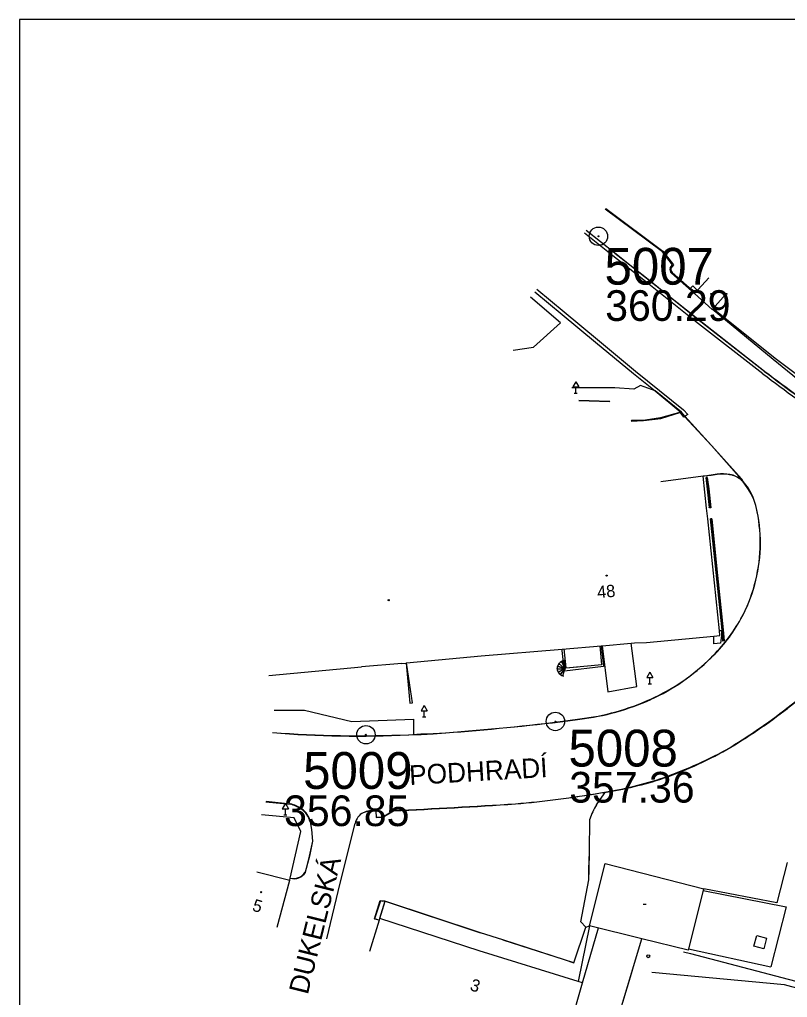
# Model space of a CAD drawing. Extents: x -590420 to -590210, y -1129531 to -1129234.
# Drawn here: x -590420.4 to -590357.8, y -1129313.6 to -1129233.9 of the extents above; entities that cross this region are included whole.
import ezdxf

# ---------------------------------------------------------------- set-up
doc = ezdxf.new("R2010")
doc.units = 0
for name, color, linetype in [('Vrstva 10', 7, 'Continuous'), ('Vrstva 15', 7, 'Continuous'), ('Vrstva 17', 7, 'Continuous'), ('Vrstva 19', 7, 'Continuous'), ('Vrstva 23', 7, 'Continuous'), ('Vrstva 4', 7, 'Continuous'), ('Vrstva 42', 7, 'Continuous'), ('Vrstva 43', 7, 'Continuous'), ('Vrstva 5', 7, 'Continuous'), ('Vrstva 63', 7, 'Continuous'), ('Vrstva 7', 7, 'Continuous'), ('Vrstva 9', 7, 'Continuous'), ('Vrstva B58', 7, 'Continuous'), ('Vrstva B59', 7, 'Continuous'), ('Vrstva B60', 7, 'Continuous')]:
    doc.layers.add(name, color=color, linetype=linetype)

msp = doc.modelspace()

# ---------------------------------------------------------------- linework, layer by layer
at = {"layer": 'Vrstva 10'}
for points in [[(-590357.78, -1129302.59), (-590358.63, -1129305.87), (-590364.59, -1129304.72)], [(-590373.92, -1129307.73), (-590374.832, -1129312.271)], [(-590366.23, -1129309.858), (-590365.68, -1129310.01), (-590339.47, -1129316.88), (-590321.05, -1129317.64), (-590313.58, -1129317.8), (-590297.47, -1129317.49), (-590297.03, -1129314.18)]]:
    msp.add_lwpolyline(points, dxfattribs=at)
at = {"layer": 'Vrstva 15'}
msp.add_line((-590369.539, -1129305.984), (-590369.289, -1129305.984), dxfattribs=at)
for centre in [(-590363.98, -1129256.221), (-590362.747, -1129256.221), (-590372.51, -1129279.184), (-590390.291, -1129281.192), (-590400.688, -1129304.994)]:
    msp.add_circle(centre, 0.0438, dxfattribs=at)
at = {"layer": 'Vrstva 17'}
for p, q in [((-590365.34, -1129256.2), (-590367.22, -1129254.53)), ((-590367.169, -1129254.474), (-590365.289, -1129256.144)), ((-590365.289, -1129256.144), (-590365.289, -1129256.144))]:
    msp.add_line(p, q, dxfattribs=at)
for points in [[(-590367.34, -1129254.09), (-590367.14, -1129253.84), (-590367.96, -1129252.78), (-590372.63, -1129249.32)], [(-590372.59, -1129249.27), (-590367.92, -1129252.73), (-590367.063, -1129253.838), (-590367.269, -1129254.108)], [(-590354.37, -1129264.78), (-590354.53, -1129265.04), (-590355.43, -1129264.41), (-590358.93, -1129261.58), (-590363.889, -1129257.476), (-590363.823, -1129257.404)], [(-590363.823, -1129257.404), (-590358.76, -1129261.47), (-590355.1, -1129264.21), (-590354.37, -1129264.78)]]:
    msp.add_lwpolyline(points, dxfattribs=at)
for centre, major_axis in [((-590366.905, -1129254.211), (0.226, -0.395)), ((-590366.907, -1129254.208), (0.188, -0.329))]:
    msp.add_ellipse(centre, major_axis=major_axis, ratio=0.984986, start_param=3.930118, end_param=4.981494, dxfattribs=at)
at = {"layer": 'Vrstva 19'}
for p, q in [((-590375.03, -1129263.377), (-590375.28, -1129263.81)), ((-590375.03, -1129263.377), (-590374.78, -1129263.81)), ((-590375.28, -1129263.81), (-590374.78, -1129263.81)), ((-590375.155, -1129264.31), (-590374.905, -1129264.31)), ((-590375.03, -1129264.31), (-590375.03, -1129263.81)), ((-590368.99, -1129287.067), (-590369.24, -1129287.5)), ((-590368.99, -1129287.067), (-590368.74, -1129287.5)), ((-590369.24, -1129287.5), (-590368.74, -1129287.5)), ((-590369.115, -1129288), (-590368.865, -1129288)), ((-590368.99, -1129288), (-590368.99, -1129287.5)), ((-590387.4, -1129289.767), (-590387.65, -1129290.2)), ((-590387.4, -1129289.767), (-590387.15, -1129290.2)), ((-590387.65, -1129290.2), (-590387.15, -1129290.2)), ((-590387.4, -1129290.7), (-590387.4, -1129290.2)), ((-590387.525, -1129290.7), (-590387.275, -1129290.7)), ((-590398.72, -1129297.767), (-590398.97, -1129298.2)), ((-590398.72, -1129297.767), (-590398.47, -1129298.2)), ((-590398.97, -1129298.2), (-590398.47, -1129298.2)), ((-590398.72, -1129298.7), (-590398.72, -1129298.2)), ((-590398.845, -1129298.7), (-590398.595, -1129298.7))]:
    msp.add_line(p, q, dxfattribs=at)
at = {"layer": 'Vrstva 23'}
for points in [[(-590365.659, -1129255.755), (-590365.289, -1129256.09), (-590365.121, -1129255.905), (-590365.491, -1129255.57)], [(-590360.5, -1129309.4), (-590360.27, -1129308.54), (-590359.459, -1129308.756), (-590359.689, -1129309.616)]]:
    msp.add_lwpolyline(points, close=True, dxfattribs=at)
msp.add_circle((-590369.12, -1129310.22), 0.125, dxfattribs=at)
at = {"layer": 'Vrstva 4'}
for p, q in [((-590364.177, -1129254.921), (-590365.34, -1129256.2)), ((-590363.91, -1129257.5), (-590365.34, -1129256.2)), ((-590362.747, -1129256.221), (-590363.91, -1129257.5)), ((-590400.07, -1129287.32), (-590392.51, -1129286.63)), ((-590376.524, -1129286.567), (-590375.948, -1129286.767)), ((-590376.398, -1129286.364), (-590375.94, -1129286.754)), ((-590376.205, -1129286.201), (-590375.928, -1129286.744)), ((-590376.56, -1129286.827), (-590375.95, -1129286.783)), ((-590376.472, -1129287.067), (-590375.946, -1129286.798)), ((-590376.297, -1129287.249), (-590375.935, -1129286.811)), ((-590376.077, -1129287.366), (-590375.921, -1129286.818)), ((-590375.947, -1129286.795), (-590375.947, -1129286.795)), ((-590375.873, -1129286.765), (-590375.873, -1129286.765)), ((-590401.06, -1129303.331), (-590398.36, -1129304.02)), ((-590399.38, -1129307.86), (-590398.36, -1129304.02))]:
    msp.add_line(p, q, dxfattribs=at)
for points in [[(-590389.22, -1129286.35), (-590388.86, -1129286.316), (-590388.827, -1129286.312), (-590382.74, -1129285.73), (-590376.138, -1129285.175), (-590372.968, -1129284.909), (-590372.875, -1129284.901), (-590370.509, -1129284.703), (-590370.24, -1129284.68), (-590369.25, -1129284.63), (-590363.77, -1129284.117), (-590363.27, -1129284.07), (-590363.31, -1129283.685), (-590363.857, -1129278.466), (-590364.267, -1129274.55), (-590364.358, -1129273.688), (-590364.63, -1129271.09), (-590368.08, -1129271.54)], [(-590376.014, -1129285.165), (-590375.83, -1129286.71), (-590372.9, -1129286.44), (-590373.028, -1129284.914)], [(-590372.875, -1129284.901), (-590372.41, -1129288.66), (-590370.04, -1129288.24), (-590370.509, -1129284.703)], [(-590386.47, -1129329.57), (-590381.1, -1129331.63), (-590378.34, -1129325.04), (-590372.97, -1129326.72), (-590372.97, -1129326.71), (-590371.23, -1129321.27), (-590370.254, -1129318.212), (-590370.11, -1129317.76), (-590370.282, -1129317.698), (-590370.284, -1129317.695), (-590372.104, -1129317.046), (-590372.11, -1129317.05), (-590375.5, -1129315.91), (-590374.48, -1129312.38), (-590374.832, -1129312.271), (-590382.92, -1129309.78), (-590391.013, -1129307.149), (-590391.04, -1129307.14), (-590391.04, -1129307.14), (-590391.078, -1129307.264), (-590391.08, -1129307.272), (-590391.87, -1129309.84)]]:
    msp.add_lwpolyline(points, dxfattribs=at)
msp.add_lwpolyline([(-590372.64, -1129302.65), (-590364.59, -1129304.72), (-590364.625, -1129304.857), (-590365.83, -1129309.614), (-590365.86, -1129309.73), (-590369.649, -1129308.79), (-590373.92, -1129307.73)], close=True, dxfattribs=at)
msp.add_circle((-590375.91, -1129286.78), 0.04, dxfattribs=at)
msp.add_circle((-590375.91, -1129286.78), 0.04, dxfattribs=at)
for start, end in [(215.00782, 232.94293), (232.94293, 250.60717)]:
    msp.add_arc((-590375.809, -1129286.602), 0.81, start, end, dxfattribs=at)
at = {"layer": 'Vrstva 5'}
for p, q in [((-590375.948, -1129286.767), (-590376.524, -1129286.567)), ((-590376.524, -1129286.567), (-590376.524, -1129286.567)), ((-590375.94, -1129286.754), (-590376.398, -1129286.364)), ((-590376.398, -1129286.364), (-590376.398, -1129286.364)), ((-590376.205, -1129286.201), (-590375.883, -1129286.07)), ((-590375.928, -1129286.744), (-590376.205, -1129286.201)), ((-590376.205, -1129286.201), (-590376.205, -1129286.201)), ((-590375.976, -1129286.108), (-590375.914, -1129286.74)), ((-590375.976, -1129286.108), (-590375.976, -1129286.108)), ((-590375.83, -1129286.71), (-590374.884, -1129286.623)), ((-590374.884, -1129286.623), (-590374.884, -1129286.623)), ((-590375.95, -1129286.783), (-590376.56, -1129286.827)), ((-590376.56, -1129286.827), (-590376.56, -1129286.827)), ((-590375.946, -1129286.798), (-590376.472, -1129287.067)), ((-590376.472, -1129287.067), (-590376.472, -1129287.067)), ((-590375.935, -1129286.811), (-590376.297, -1129287.249)), ((-590376.297, -1129287.249), (-590376.297, -1129287.249)), ((-590376.077, -1129287.366), (-590376.077, -1129287.366)), ((-590375.83, -1129286.71), (-590375.83, -1129286.71))]:
    msp.add_line(p, q, dxfattribs=at)
msp.add_lwpolyline([(-590389.22, -1129286.35), (-590392.51, -1129286.63)], dxfattribs=at)
for centre, radius, start, end in [((-590376.027, -1129286.768), 0.536, 158.02047, 186.35954), ((-590375.797, -1129286.878), 0.791, 139.43926, 156.88044), ((-590375.797, -1129286.878), 0.791, 121.10978, 139.43926), ((-590375.797, -1129286.878), 0.791, 103.07973, 121.10978), ((-590376.027, -1129286.768), 0.536, 186.35954, 213.92649)]:
    msp.add_arc(centre, radius, start, end, dxfattribs=at)
for centre, major_axis, ratio, start_param, end_param in [((-590375.754, -1129286.753), (-0.808, -0.043), 0.804719, 5.928327, 6.719832), ((-590375.441, -1129287.099), (-1.027, 0.639), 0.799712, 5.902988, 6.408068), ((-590375.573, -1129286.258), (-0.693, -1.013), 0.808425, 5.991235, 6.532866)]:
    msp.add_ellipse(centre, major_axis=major_axis, ratio=ratio, start_param=start_param, end_param=end_param, dxfattribs=at)
at = {"layer": 'Vrstva 63'}
for p, q in [((-590210.408, -1129233.852), (-590420.408, -1129233.852)), ((-590420.408, -1129233.852), (-590420.408, -1129530.852))]:
    msp.add_line(p, q, dxfattribs=at)
at = {"layer": 'Vrstva 7'}
for p, q in [((-590378.37, -1129256.06), (-590376.13, -1129257.91)), ((-590378.36, -1129256.04), (-590376.13, -1129257.91)), ((-590371.83, -1129263.89), (-590375.35, -1129263.89)), ((-590374.78, -1129264.88), (-590372.269, -1129264.959)), ((-590366.202, -1129266.264), (-590366.501, -1129265.872)), ((-590366.202, -1129266.267), (-590366.501, -1129265.872)), ((-590366.449, -1129265.855), (-590366.162, -1129266.227)), ((-590366.13, -1129266.2), (-590366.41, -1129265.87)), ((-590370.49, -1129266.55), (-590370.52, -1129266.6)), ((-590366.15, -1129266.22), (-590366.202, -1129266.267)), ((-590361.54, -1129271.39), (-590361.38, -1129271.54)), ((-590361.53, -1129271.37), (-590361.36, -1129271.52)), ((-590361.36, -1129271.52), (-590361.5, -1129271.35)), ((-590361.36, -1129271.52), (-590361.49, -1129271.33)), ((-590360.98, -1129272.08), (-590361.38, -1129271.54)), ((-590360.95, -1129272.07), (-590361.36, -1129271.52)), ((-590364.147, -1129273.658), (-590364.141, -1129273.648)), ((-590364.131, -1129273.657), (-590364.127, -1129273.648)), ((-590364.02, -1129273.65), (-590364.131, -1129273.657)), ((-590364.041, -1129273.643), (-590364.127, -1129273.648)), ((-590364.02, -1129273.65), (-590364.041, -1129273.643)), ((-590363.94, -1129274.55), (-590364.048, -1129274.558)), ((-590364.048, -1129274.558), (-590364.036, -1129274.568)), ((-590363.95, -1129274.56), (-590364.036, -1129274.568)), ((-590363.95, -1129274.56), (-590363.94, -1129274.55)), ((-590363.14, -1129283.68), (-590363.31, -1129283.685)), ((-590372.968, -1129284.909), (-590372.77, -1129286.61)), ((-590362.93, -1129284.51), (-590363.03, -1129284.519)), ((-590357.8, -1129289.99), (-590352.24, -1129285.71)), ((-590352.24, -1129285.73), (-590357.76, -1129290.01)), ((-590375.69, -1129291.04), (-590374.7, -1129290.9)), ((-590375.68, -1129291.01), (-590374.7, -1129290.87)), ((-590400.32, -1129297.63), (-590398.32, -1129297.82)), ((-590400.3, -1129297.59), (-590398.31, -1129297.8)), ((-590391.34, -1129298.39), (-590391.354, -1129298.407)), ((-590396.71, -1129299.27), (-590396.59, -1129299.9)), ((-590396.56, -1129299.89), (-590396.68, -1129299.27)), ((-590396.48, -1129300.84), (-590396.56, -1129299.89)), ((-590391.013, -1129307.149), (-590390.58, -1129305.74)), ((-590390.99, -1129305.67), (-590390.8, -1129305.74)), ((-590390.6, -1129305.73), (-590390.58, -1129305.74)), ((-590391.46, -1129307.18), (-590391.455, -1129307.176)), ((-590374.48, -1129312.38), (-590373.166, -1129307.917)), ((-590374.21, -1129307.86), (-590373.92, -1129307.73)), ((-590372.104, -1129317.046), (-590369.649, -1129308.79)), ((-590365.83, -1129309.614), (-590359.109, -1129311.088)), ((-590372.11, -1129317.05), (-590370.41, -1129311.35))]:
    msp.add_line(p, q, dxfattribs=at)
for points in [[(-590359.77, -1129262.73), (-590365.26, -1129258.46), (-590369.6, -1129255), (-590372, -1129253.11), (-590374.33, -1129251.27)], [(-590359.62, -1129262.54), (-590365.08, -1129258.29), (-590369.42, -1129254.82), (-590371.84, -1129252.89), (-590374.17, -1129251.04)], [(-590371.84, -1129252.89), (-590369.4, -1129254.81), (-590365.08, -1129258.27), (-590359.6, -1129262.54)], [(-590378.21, -1129255.83), (-590375.98, -1129257.69), (-590373.27, -1129259.95), (-590370.16, -1129262.52), (-590366.23, -1129265.66), (-590365.89, -1129266.05), (-590366.13, -1129266.2)], [(-590376.13, -1129257.91), (-590373.42, -1129260.15), (-590370.31, -1129262.72), (-590368.56, -1129264.11)], [(-590368.56, -1129264.11), (-590369.76, -1129263.68), (-590370.3, -1129263.98), (-590371.83, -1129263.89)], [(-590366.41, -1129265.87), (-590368.56, -1129264.11)], [(-590368.56, -1129264.11), (-590366.449, -1129265.855)], [(-590374.78, -1129264.91), (-590372.26, -1129264.98), (-590372.269, -1129264.959)], [(-590370.52, -1129266.6), (-590369.51, -1129266.55), (-590368.09, -1129266.39), (-590366.449, -1129265.855)], [(-590366.449, -1129265.855), (-590368.11, -1129266.33), (-590369.53, -1129266.54), (-590370.49, -1129266.55)], [(-590366.162, -1129266.227), (-590366.202, -1129266.264), (-590366.202, -1129266.267)], [(-590366.13, -1129266.2), (-590366.15, -1129266.22), (-590366.162, -1129266.227)], [(-590361.5, -1129271.35), (-590363.97, -1129268.59), (-590366.15, -1129266.22)], [(-590366.13, -1129266.2), (-590363.95, -1129268.58), (-590361.49, -1129271.33)], [(-590363.49, -1129270.92), (-590363.98, -1129271), (-590364.52, -1129271.07), (-590364.63, -1129271.09)], [(-590363.49, -1129270.95), (-590363.99, -1129271.02), (-590364.52, -1129271.08), (-590364.63, -1129271.09)], [(-590364.3, -1129271.19), (-590364.399, -1129271.201)], [(-590364.399, -1129271.201), (-590364.285, -1129272.131), (-590364.131, -1129273.657)], [(-590364.127, -1129273.648), (-590364.279, -1129272.141), (-590364.399, -1129271.201)], [(-590364.3, -1129271.19), (-590364.18, -1129272.12), (-590364.02, -1129273.65)], [(-590364.041, -1129273.643), (-590364.18, -1129272.13), (-590364.3, -1129271.19)], [(-590363.03, -1129284.519), (-590363.097, -1129283.63), (-590363.64, -1129278.407), (-590364.048, -1129274.558)], [(-590364.036, -1129274.568), (-590363.63, -1129278.405), (-590363.09, -1129283.627), (-590363.03, -1129284.519)], [(-590362.93, -1129284.51), (-590363.02, -1129283.62), (-590363.55, -1129278.4), (-590363.95, -1129274.56)], [(-590363.94, -1129274.55), (-590363.54, -1129278.4), (-590363, -1129283.62), (-590362.93, -1129284.51)], [(-590363.14, -1129283.68), (-590363.15, -1129284.07), (-590363.21, -1129284.7), (-590363.77, -1129284.75), (-590363.77, -1129284.117)], [(-590372.77, -1129286.61), (-590375.95, -1129286.98), (-590376.13, -1129285.29), (-590376.138, -1129285.175)], [(-590388.86, -1129286.316), (-590388.56, -1129289.59), (-590388.36, -1129289.57), (-590388.827, -1129286.312)], [(-590399.63, -1129290.16), (-590397.15, -1129290.16), (-590393.301, -1129291.094), (-590388.27, -1129290.89), (-590388.26, -1129292.02), (-590388.259, -1129292.136)], [(-590388.67, -1129292.18), (-590387.64, -1129292.14), (-590386.67, -1129292.08), (-590385.65, -1129292.01)], [(-590388.65, -1129292.16), (-590387.66, -1129292.1), (-590386.66, -1129292.05), (-590385.64, -1129292)], [(-590373.35, -1129297.88), (-590372.72, -1129296.99), (-590372.621, -1129296.851)], [(-590391.354, -1129298.407), (-590391.326, -1129298.897), (-590390.77, -1129298.88), (-590389.89, -1129298.36)], [(-590391.34, -1129298.39), (-590391.32, -1129298.89), (-590390.79, -1129298.87), (-590389.92, -1129298.34)], [(-590395.33, -1129308.81), (-590394.24, -1129304.25), (-590393.02, -1129299.39)], [(-590373.96, -1129303.98), (-590373.96, -1129303.16), (-590373.92, -1129301.7), (-590373.87, -1129299.04)], [(-590373.96, -1129303.98), (-590373.95, -1129303.16), (-590373.9, -1129301.71), (-590373.87, -1129299.04)], [(-590396.59, -1129299.9), (-590396.5, -1129300.83), (-590396.76, -1129302.06), (-590397.11, -1129303.37)], [(-590397.08, -1129303.38), (-590396.75, -1129302.07), (-590396.48, -1129300.84)], [(-590375.18, -1129310.76), (-590374.21, -1129307.86), (-590374.61, -1129307.41), (-590373.96, -1129303.98)], [(-590364.625, -1129304.857), (-590357.86, -1129306.2), (-590359.109, -1129311.088)], [(-590391.08, -1129307.272), (-590391.46, -1129307.18), (-590390.99, -1129305.67)], [(-590390.97, -1129305.69), (-590391.455, -1129307.176), (-590391.078, -1129307.264)], [(-590390.6, -1129305.73), (-590391.047, -1129307.138), (-590391.04, -1129307.14)], [(-590390.6, -1129305.73), (-590390.8, -1129305.74), (-590390.97, -1129305.69), (-590390.99, -1129305.67)], [(-590382.79, -1129308.3), (-590390.6, -1129305.73)], [(-590390.58, -1129305.74), (-590382.8, -1129308.32), (-590382.79, -1129308.3)], [(-590380.97, -1129308.89), (-590382.8, -1129308.32)], [(-590380.97, -1129308.88), (-590382.79, -1129308.3)], [(-590375.18, -1129310.76), (-590375.96, -1129310.51), (-590380.97, -1129308.88)], [(-590380.97, -1129308.88), (-590380.97, -1129308.89), (-590375.97, -1129310.5), (-590375.18, -1129310.76)], [(-590300.68, -1129317.99), (-590311.82, -1129318.26), (-590320.49, -1129318.55), (-590330.07, -1129318.36), (-590338.22, -1129317.93), (-590347.27, -1129315.46), (-590357.99, -1129312.56), (-590368.83, -1129311.54)]]:
    msp.add_lwpolyline(points, dxfattribs=at)
for centre, major_axis, ratio, start_param, end_param in [((-590290.666, -1129172.172), (113.957, 0), 0.999394, 4.060851, 4.121508), ((-590311.072, -1129200.348), (74.306, -27.239), 0.996591, 4.401942, 4.489079), ((-590300.332, -1129185.077), (-91.864, -32.809), 0.999599, 0.574857, 0.645547), ((-590362.993, -1129274.87), (-3.455, 2.106), 0.973966, 5.112478, 5.372051), ((-590363.035, -1129273.709), (1.136, 2.566), 0.988802, 0.219997, 0.585453), ((-590362.721, -1129272.728), (-1.636, 0.749), 0.990971, 4.421053, 5.003725), ((-590362.668, -1129272.607), (-1.658, 0.585), 0.948537, 4.326719, 4.910517), ((-590365.286, -1129274.859), (5.04, -0.98), 0.996227, 0.365497, 0.767095), ((-590365.193, -1129274.73), (-4.08, 2.964), 0.992083, 3.927767, 4.332557), ((-590372.567, -1129276.594), (11.344, 5.528), 0.993582, 5.798102, 6.038644), ((-590373.03, -1129276.573), (11.435, 6.325), 0.993586, 5.745474, 5.975994), ((-590373.185, -1129276.456), (12.742, -3.475), 0.995904, 6.055982, 6.512151), ((-590373.262, -1129276.454), (13.028, 2.703), 0.995054, 5.585564, 6.039391), ((-590372.383, -1129277.107), (10.93, 5.734), 0.982467, 4.984436, 5.314463), ((-590373.77, -1129275.904), (13.994, 0.422), 0.995021, 5.455693, 5.743261), ((-590375.816, -1129274.26), (16.515, 2.292), 0.99106, 5.002119, 5.361718), ((-590375.655, -1129274.352), (16.378, 1.772), 0.992013, 5.027401, 5.392437), ((-590376.962, -1129271.76), (16.097, -10.585), 0.998099, 5.410971, 5.724683), ((-590377.203, -1129270.733), (5.463, -19.574), 0.998752, 6.13435, 6.431051), ((-590387.046, -1129253.843), (43.853, 20.728), 0.956309, 4.818033, 4.941033), ((-590386.782, -1129253.578), (44.345, 17.54), 0.97467, 4.875795, 5.001317), ((-590403.376, -1129067.762), (221.308, -47.672), 0.993086, 5.001538, 5.045774), ((-590401.193, -1129090.944), (189.678, -70.279), 0.996273, 5.143009, 5.192531), ((-590392.84, -1129199.439), (92.402, -14.632), 0.991794, 4.794006, 4.912976), ((-590392.916, -1129205.065), (86.565, -14.731), 0.992946, 4.801627, 4.92816), ((-590378.712, -1129264.919), (30.37, -12.04), 0.998305, 5.41755, 5.601588), ((-590378.794, -1129264.188), (14.898, -29.795), 0.999049, 6.143999, 6.323448), ((-590377.597, -1129265.776), (20.668, -23.749), 0.998615, 5.712701, 5.870381), ((-590377.655, -1129266.212), (-9.931, -29.416), 0.998638, 0.476678, 0.636849), ((-590387.902, -1129209.9), (81.321, -34.813), 0.996917, 5.205705, 5.28511), ((-590388.551, -1129205.369), (86.764, -33.731), 0.996513, 5.174568, 5.249808), ((-590398.987, -1129300.494), (-2.607, 1.171), 0.963267, 4.540823, 4.883955), ((-590398.814, -1129300.156), (-2.156, 1.133), 0.9882, 4.575163, 4.982286), ((-590423.495, -1128784.686), (599.959, 0), 0.857493, 4.76838, 4.785016), ((-590405.778, -1129025.028), (325.315, 2.538), 0.841291, 4.754684, 4.785303), ((-590398.352, -1129299.619), (-1.397, 0.936), 0.996426, 3.943029, 4.719956), ((-590398.274, -1129299.575), (-0.103, 1.621), 0.998972, 4.838094, 5.658591), ((-590391.82, -1129299.605), (-1.191, -0.263), 0.997524, 4.963157, 5.887239), ((-590391.637, -1129300.158), (-1.426, 1.09), 0.998498, 5.197961, 5.785113), ((-590391.594, -1129300.545), (-2.349, -0.052), 0.914057, 4.589447, 5.028392), ((-590368.441, -1129300.777), (-4.743, 3.162), 0.999873, 0.054801, 0.278324), ((-590398.023, -1129302.786), (1.108, 0.12), 0.999611, 4.331448, 5.612957), ((-590398.034, -1129302.795), (0.254, 1.059), 0.999554, 3.110086, 4.390849)]:
    msp.add_ellipse(centre, major_axis=major_axis, ratio=ratio, start_param=start_param, end_param=end_param, dxfattribs=at)
at = {"layer": 'Vrstva 9'}
for points in [[(-590380.14, -1129260.82), (-590378.48, -1129260.56), (-590376.27, -1129258.57), (-590378.73, -1129256.49)], [(-590398.36, -1129304.02), (-590398.324, -1129303.859), (-590398.321, -1129303.845), (-590397.47, -1129300.06), (-590397.99, -1129298.93), (-590400.66, -1129298.69)]]:
    msp.add_lwpolyline(points, dxfattribs=at)
at = {"layer": 'Vrstva B60'}
for centre, radius in [((-590373.18, -1129251.52), 0.75), ((-590373.18, -1129251.52), 0.0358), ((-590376.69, -1129291.08), 0.75), ((-590392.15, -1129292.16), 0.75), ((-590376.69, -1129291.08), 0.0358), ((-590392.15, -1129292.16), 0.0358)]:
    msp.add_circle(centre, radius, dxfattribs=at)

# ---------------------------------------------------------------- texts
at = {"layer": 'Vrstva 42'}
for s, rotation, p in [('PODHRADÍ', 3.34682, (-590388.571, -1129296.265)), ('DUKELSKÁ', 76.10331, (-590396.898, -1129313.41))]:
    msp.add_text(s, height=1.6, rotation=rotation, dxfattribs=at).set_placement(p)
at = {"layer": 'Vrstva 43'}
for s, rotation, p in [('48', 5.41761, (-590373.244, -1129281.043)), ('5', 343.84438, (-590401.484, -1129306.493)), ('3', 342.1982, (-590383.733, -1129312.969))]:
    msp.add_text(s, height=1, rotation=rotation, dxfattribs=at).set_placement(p)
at = {"layer": 'Vrstva B58'}
for s, p in [('360.29', (-590372.628, -1129258.421)), ('357.36', (-590375.56, -1129297.692)), ('356.85', (-590398.827, -1129299.609))]:
    msp.add_text(s, height=2.5, dxfattribs=at).set_placement(p)
at = {"layer": 'Vrstva B59'}
for s, p in [('5007', (-590372.684, -1129255.465)), ('5008', (-590375.624, -1129294.755)), ('5009', (-590397.272, -1129296.577))]:
    msp.add_text(s, height=3, dxfattribs=at).set_placement(p)

doc.saveas('drawing.dxf')
